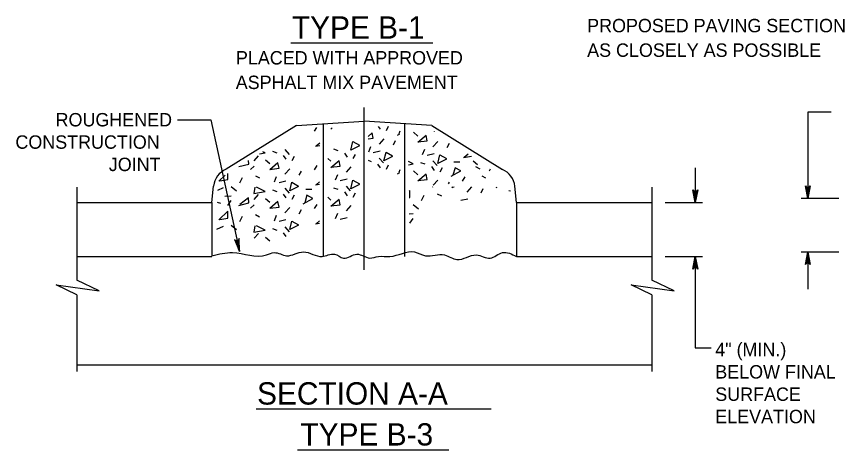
# Model space of a CAD drawing. Extents: x -7.6 to -0.4, y 98.1 to 108.3.
# Drawn here: x -7.303 to -3.651, y 104.4 to 106.341 of the extents above; entities that cross this region are included whole.
import ezdxf

# ---------------------------------------------------------------- set-up
doc = ezdxf.new("R2010")
doc.units = 0
for name, color, linetype in [('DETL-DIMS', 7, 'Continuous'), ('DETL-LINE', 7, 'Continuous'), ('DETL-NOTE', 7, 'Continuous'), ('DETL-PATT', 7, 'Continuous'), ('DETL-TITL', 7, 'Continuous')]:
    doc.layers.add(name, color=color, linetype=linetype)

msp = doc.modelspace()

# ---------------------------------------------------------------- linework, layer by layer
at = {"layer": 'DETL-DIMS'}
for p, q in [((-5.7445, 105.2058), (-5.7445, 105.9322)), ((-3.6535, 105.9115), (-3.7581, 105.9115)), ((-3.7581, 105.9115), (-3.7581, 105.5249)), ((-6.5803, 105.8778), (-6.432, 105.8778)), ((-6.432, 105.8778), (-6.3025, 105.2883)), ((-4.2616, 105.6624), (-4.2616, 105.5079)), ((-4.3961, 105.5079), (-4.2295, 105.5079)), ((-3.4196, 105.5249), (-3.7881, 105.5249)), ((-4.3961, 105.2655), (-4.2295, 105.2655)), ((-4.2616, 105.2655), (-4.2616, 104.8568)), ((-3.3833, 105.2855), (-3.7881, 105.2855)), ((-3.7581, 105.2855), (-3.7581, 105.1192)), ((-4.2616, 104.8568), (-4.1905, 104.8568))]:
    msp.add_line(p, q, dxfattribs=at)
for points in [[(-3.7581, 105.5249), (-3.7686, 105.5814), (-3.7656, 105.577), (-3.7618, 105.5748), (-3.7581, 105.5741), (-3.7543, 105.5748), (-3.7505, 105.577), (-3.7475, 105.5814), (-3.7581, 105.5249), (-3.7505, 105.577), (-3.7543, 105.5748), (-3.7581, 105.5249), (-3.7581, 105.5741), (-3.7618, 105.5748), (-3.7581, 105.5249), (-3.7656, 105.577)], [(-4.2616, 105.5079), (-4.2722, 105.5644), (-4.2692, 105.5601), (-4.2654, 105.5578), (-4.2616, 105.5572), (-4.2578, 105.5578), (-4.254, 105.5601), (-4.251, 105.5644), (-4.2616, 105.5079), (-4.254, 105.5601), (-4.2578, 105.5578), (-4.2616, 105.5079), (-4.2616, 105.5572), (-4.2654, 105.5578), (-4.2616, 105.5079), (-4.2692, 105.5601)], [(-6.3025, 105.2883), (-6.3043, 105.3457), (-6.3063, 105.3408), (-6.3095, 105.3378), (-6.3131, 105.3364), (-6.3169, 105.3362), (-6.3211, 105.3376), (-6.3249, 105.3412), (-6.3025, 105.2883), (-6.3211, 105.3376), (-6.3169, 105.3362), (-6.3025, 105.2883), (-6.3131, 105.3364), (-6.3095, 105.3378), (-6.3025, 105.2883), (-6.3063, 105.3408)], [(-4.2616, 105.2655), (-4.251, 105.209), (-4.254, 105.2134), (-4.2578, 105.2156), (-4.2616, 105.2163), (-4.2654, 105.2156), (-4.2692, 105.2134), (-4.2722, 105.209), (-4.2616, 105.2655), (-4.2692, 105.2134), (-4.2654, 105.2156), (-4.2616, 105.2655), (-4.2616, 105.2163), (-4.2578, 105.2156), (-4.2616, 105.2655), (-4.254, 105.2134)], [(-3.7581, 105.2855), (-3.7475, 105.229), (-3.7505, 105.2333), (-3.7543, 105.2356), (-3.7581, 105.2362), (-3.7618, 105.2356), (-3.7656, 105.2333), (-3.7686, 105.229), (-3.7581, 105.2855), (-3.7656, 105.2333), (-3.7618, 105.2356), (-3.7581, 105.2855), (-3.7581, 105.2362), (-3.7543, 105.2356), (-3.7581, 105.2855), (-3.7505, 105.2333)]]:
    msp.add_lwpolyline(points, dxfattribs=at)
at = {"layer": 'DETL-LINE'}
for p, q in [((-6.0475, 105.8514), (-5.7445, 105.8716)), ((-5.4415, 105.8514), (-5.7445, 105.8716)), ((-6.0475, 105.8514), (-6.363, 105.6558)), ((-5.9263, 105.2655), (-5.9263, 105.8594)), ((-5.5627, 105.2655), (-5.5627, 105.8594)), ((-5.4415, 105.8514), (-5.1259, 105.655)), ((-6.4263, 105.5079), (-6.419, 105.5807)), ((-5.0628, 105.5079), (-5.07, 105.58)), ((-7.0323, 105.5762), (-7.0323, 105.1599)), ((-4.4567, 105.5762), (-4.4567, 105.1599)), ((-7.0323, 105.5079), (-6.4263, 105.5079)), ((-6.4263, 105.5079), (-6.4263, 105.2685)), ((-5.0628, 105.5079), (-4.4567, 105.5079)), ((-5.0628, 105.5079), (-5.0628, 105.2655)), ((-7.0323, 105.2655), (-6.4263, 105.2655)), ((-5.0628, 105.2655), (-4.4567, 105.2655)), ((-7.0323, 105.0935), (-7.0323, 104.7507)), ((-4.4567, 105.0934), (-4.4567, 104.7507)), ((-7.0323, 104.7807), (-4.4567, 104.7807))]:
    msp.add_line(p, q, dxfattribs=at)
for points in [[(-7.032, 105.0934), (-7.1239, 105.1384), (-6.9317, 105.1122), (-7.032, 105.1599)], [(-4.4567, 105.0934), (-4.5486, 105.1384), (-4.3564, 105.1122), (-4.4567, 105.1599)]]:
    msp.add_lwpolyline(points, dxfattribs=at)
for centre, start, end in [((-6.3285, 105.5717), 112.2917, 174.2894), ((-5.1605, 105.5709), 5.7107, 67.6341)]:
    msp.add_arc(centre, 0.0909, start, end, dxfattribs=at)
msp.add_spline([(-6.4263, 105.2685), (-6.3341, 105.2827), (-6.1821, 105.2723), (-6.1476, 105.2827), (-6.0923, 105.2689), (-6.0164, 105.2861), (-5.9335, 105.2654), (-5.8782, 105.2758), (-5.8368, 105.2585), (-5.778, 105.2758), (-5.7193, 105.2585), (-5.6813, 105.2654), (-5.6295, 105.2654), (-5.519, 105.2861), (-5.4707, 105.2689), (-5.3843, 105.2723), (-5.3291, 105.2516), (-5.2427, 105.2723), (-5.1805, 105.2585), (-5.1253, 105.2827), (-5.0628, 105.2655)], degree=3, dxfattribs=at)
at = {"layer": 'DETL-PATT'}
for p, q in [((-5.9674, 105.8263), (-5.9569, 105.8431)), ((-5.8878, 105.8409), (-5.8935, 105.8359)), ((-5.6814, 105.8473), (-5.6732, 105.8358)), ((-5.6373, 105.8473), (-5.6467, 105.8286)), ((-5.5962, 105.8093), (-5.5855, 105.8152)), ((-5.5855, 105.8261), (-5.5889, 105.8141)), ((-5.5232, 105.8218), (-5.5039, 105.8049)), ((-5.4319, 105.8245), (-5.4317, 105.8242)), ((-5.9625, 105.7589), (-5.9433, 105.7621)), ((-5.9433, 105.7734), (-5.9602, 105.7589)), ((-5.6563, 105.7924), (-5.678, 105.7684)), ((-5.6058, 105.7828), (-5.6154, 105.7636)), ((-5.4149, 105.7809), (-5.4365, 105.7568)), ((-5.3643, 105.7713), (-5.3739, 105.752)), ((-6.1551, 105.7372), (-6.1359, 105.73)), ((-6.0998, 105.7445), (-6.0805, 105.7228)), ((-5.8814, 105.7469), (-5.8622, 105.7397)), ((-5.8333, 105.7277), (-5.8213, 105.7108)), ((-5.7165, 105.7563), (-5.7261, 105.7323)), ((-5.6732, 105.7371), (-5.7045, 105.7299)), ((-5.475, 105.7448), (-5.4847, 105.7207)), ((-5.4317, 105.7255), (-5.463, 105.7183)), ((-6.2369, 105.6939), (-6.2177, 105.7156)), ((-6.1864, 105.6987), (-6.1671, 105.6819)), ((-6.107, 105.718), (-6.0949, 105.7011)), ((-6.0588, 105.7132), (-6.0685, 105.6939)), ((-5.9074, 105.7038), (-5.8935, 105.6916)), ((-5.7852, 105.7228), (-5.7948, 105.7036)), ((-5.7272, 105.6963), (-5.7141, 105.6914)), ((-5.678, 105.7058), (-5.6587, 105.6841)), ((-5.4365, 105.6942), (-5.4173, 105.6726)), ((-5.3427, 105.6894), (-5.3162, 105.6894)), ((-5.2993, 105.7087), (-5.2646, 105.7145)), ((-5.2791, 105.724), (-5.2969, 105.7087)), ((-5.256, 105.6942), (-5.2368, 105.6774)), ((-6.2538, 105.6554), (-6.2369, 105.6698)), ((-6.0781, 105.6578), (-6.0998, 105.6337)), ((-5.9674, 105.653), (-5.9553, 105.6723)), ((-5.8044, 105.6675), (-5.8261, 105.6434)), ((-5.6852, 105.6793), (-5.6732, 105.6625)), ((-5.6371, 105.6745), (-5.6467, 105.6553)), ((-5.5855, 105.6528), (-5.5889, 105.6408)), ((-5.4919, 105.687), (-5.4726, 105.6798)), ((-5.4438, 105.6678), (-5.4317, 105.6509)), ((-5.3956, 105.6629), (-5.4052, 105.6437)), ((-5.2464, 105.6678), (-5.2271, 105.6581)), ((-5.1838, 105.6485), (-5.1785, 105.6578)), ((-6.367, 105.6295), (-6.3958, 105.6024)), ((-6.3019, 105.5952), (-6.2899, 105.6193)), ((-6.2321, 105.6265), (-6.2129, 105.6169)), ((-6.1383, 105.6217), (-6.1479, 105.5976)), ((-6.0275, 105.6482), (-6.0372, 105.6289)), ((-5.8646, 105.6314), (-5.8742, 105.6073)), ((-5.5962, 105.636), (-5.5855, 105.6419)), ((-5.5232, 105.6485), (-5.5039, 105.6317)), ((-5.3042, 105.6028), (-5.2921, 105.622)), ((-5.2175, 105.6268), (-5.2007, 105.6172)), ((-6.3404, 105.5784), (-6.3164, 105.5591)), ((-6.0949, 105.6024), (-6.1262, 105.5952)), ((-5.9625, 105.5856), (-5.9443, 105.5886)), ((-5.9443, 105.5992), (-5.9602, 105.5856)), ((-5.8213, 105.6121), (-5.8526, 105.6049)), ((-5.8261, 105.5808), (-5.8068, 105.5592)), ((-5.4149, 105.6076), (-5.4358, 105.5843)), ((-5.3643, 105.5979), (-5.3683, 105.5901)), ((-6.3765, 105.5736), (-6.4014, 105.5611)), ((-6.2369, 105.5206), (-6.2177, 105.5423)), ((-6.1551, 105.5639), (-6.1359, 105.5567)), ((-6.107, 105.5447), (-6.0949, 105.5278)), ((-6.0998, 105.5712), (-6.0805, 105.5495)), ((-6.0059, 105.5663), (-5.9794, 105.5663)), ((-5.8814, 105.5736), (-5.8622, 105.5664)), ((-5.8333, 105.5543), (-5.8213, 105.5375)), ((-5.7852, 105.5495), (-5.7948, 105.5303)), ((-5.4393, 105.5755), (-5.4378, 105.5767)), ((-5.4176, 105.5466), (-5.3983, 105.537)), ((-5.3526, 105.5755), (-5.3423, 105.5767)), ((-5.3484, 105.5767), (-5.3526, 105.5731)), ((-5.2646, 105.5767), (-5.2852, 105.5539)), ((-5.213, 105.5683), (-5.2226, 105.5491)), ((-5.1528, 105.5731), (-5.1506, 105.5767)), ((-5.0975, 105.5611), (-5.0897, 105.5589)), ((-6.403, 105.5081), (-6.3886, 105.5038)), ((-6.3693, 105.5351), (-6.3404, 105.5375)), ((-6.3549, 105.4941), (-6.3404, 105.5158)), ((-6.1864, 105.5254), (-6.1671, 105.5086)), ((-6.0588, 105.5399), (-6.0685, 105.5206)), ((-5.9074, 105.5305), (-5.8935, 105.5182)), ((-5.4874, 105.5154), (-5.4754, 105.5394)), ((-5.2804, 105.5226), (-5.3117, 105.5154)), ((-6.2538, 105.4821), (-6.2369, 105.4966)), ((-6.0781, 105.4845), (-6.0998, 105.4604)), ((-6.0275, 105.4749), (-6.0372, 105.4556)), ((-5.9674, 105.4797), (-5.9553, 105.4989)), ((-5.8044, 105.4942), (-5.8261, 105.4701)), ((-5.5259, 105.4985), (-5.5018, 105.4793)), ((-6.3019, 105.4219), (-6.2899, 105.446)), ((-6.2321, 105.4532), (-6.2129, 105.4436)), ((-6.1383, 105.4484), (-6.1479, 105.4243)), ((-5.8646, 105.4581), (-5.8742, 105.434)), ((-5.8213, 105.4388), (-5.8526, 105.4316)), ((-5.5437, 105.4561), (-5.5259, 105.4576)), ((-5.5403, 105.4143), (-5.5259, 105.4359)), ((-6.3765, 105.4003), (-6.4054, 105.3858)), ((-6.3404, 105.4051), (-6.3164, 105.3858)), ((-6.0949, 105.4292), (-6.1262, 105.4219)), ((-6.0998, 105.3979), (-6.0805, 105.3762)), ((-5.9625, 105.4123), (-5.9453, 105.4152)), ((-5.9453, 105.4251), (-5.9602, 105.4123)), ((-6.2369, 105.3473), (-6.2177, 105.369)), ((-6.1551, 105.3907), (-6.1359, 105.3834)), ((-6.107, 105.3714), (-6.0949, 105.3546)), ((-6.1864, 105.3521), (-6.1671, 105.3353))]:
    msp.add_line(p, q, dxfattribs=at)
for points in [[(-5.7272, 105.7922), (-5.7045, 105.7949), (-5.7093, 105.8189), (-5.7272, 105.8034)], [(-5.5039, 105.7785), (-5.463, 105.7833), (-5.4678, 105.8073), (-5.5039, 105.7761)], [(-5.7659, 105.7613), (-5.8044, 105.7421), (-5.7948, 105.7806), (-5.7659, 105.7638)], [(-6.2132, 105.7254), (-6.1888, 105.73), (-6.1982, 105.7347)], [(-5.6178, 105.713), (-5.6563, 105.6938), (-5.6467, 105.7323), (-5.6178, 105.7154)], [(-6.3058, 105.6677), (-6.261, 105.6795), (-6.2627, 105.6946)], [(-5.8935, 105.6651), (-5.8526, 105.6699), (-5.8574, 105.6939), (-5.8935, 105.6627)], [(-5.5469, 105.6757), (-5.5256, 105.6798), (-5.5469, 105.6904)], [(-5.3764, 105.7014), (-5.4149, 105.6822), (-5.4052, 105.7207), (-5.3764, 105.7039)], [(-6.1671, 105.6554), (-6.1262, 105.6602), (-6.131, 105.6843), (-6.1671, 105.653)], [(-5.3547, 105.6244), (-5.3114, 105.6485), (-5.3378, 105.6629), (-5.3475, 105.6292)], [(-6.391, 105.6049), (-6.3549, 105.6097), (-6.3549, 105.6371)], [(-5.5039, 105.6052), (-5.463, 105.61), (-5.4678, 105.6341), (-5.5039, 105.6028)], [(-6.0396, 105.5784), (-6.0781, 105.5591), (-6.0685, 105.5976), (-6.0396, 105.5808)], [(-5.7659, 105.5881), (-5.8044, 105.5688), (-5.7948, 105.6073), (-5.7659, 105.5904)], [(-6.2345, 105.576), (-6.2393, 105.5471), (-6.1888, 105.5567), (-6.2273, 105.576)], [(-5.5437, 105.5294), (-5.5403, 105.5298), (-5.5403, 105.5611), (-5.5437, 105.558)], [(-6.3067, 105.4941), (-6.261, 105.5062), (-6.2634, 105.5278), (-6.3019, 105.4989)], [(-6.1671, 105.4821), (-6.1262, 105.4869), (-6.131, 105.511), (-6.1671, 105.4797)], [(-6.0179, 105.5014), (-5.9746, 105.5254), (-6.0011, 105.5399), (-6.0107, 105.5062)], [(-5.8935, 105.4918), (-5.8526, 105.4966), (-5.8574, 105.5207), (-5.8935, 105.4894)], [(-6.391, 105.4316), (-6.3549, 105.4364), (-6.3549, 105.4677), (-6.3958, 105.4292)], [(-6.2345, 105.4027), (-6.2393, 105.3738), (-6.1888, 105.3834), (-6.2273, 105.4027)], [(-6.0396, 105.4051), (-6.0781, 105.3858), (-6.0685, 105.4243), (-6.0396, 105.4075)]]:
    msp.add_lwpolyline(points, dxfattribs=at)
at = {"layer": 'DETL-TITL'}
for p, q in [((-6.0731, 106.2222), (-5.4375, 106.2222)), ((-6.2287, 104.5838), (-5.1763, 104.5838)), ((-6.0438, 104.4005), (-5.366, 104.4005))]:
    msp.add_line(p, q, dxfattribs=at)

# ---------------------------------------------------------------- texts
at = {"layer": 'DETL-NOTE'}
for s, p in [('PROPOSED PAVING SECTION', (-4.746, 106.2693)), ('AS CLOSELY AS POSSIBLE', (-4.746, 106.1593)), ('PLACED WITH APPROVED', (-6.3191, 106.1251)), ('ASPHALT MIX PAVEMENT', (-6.3199, 106.0151)), ('ROUGHENED', (-7.1268, 105.8478)), ('CONSTRUCTION', (-7.3068, 105.7478)), ('JOINT', (-6.8884, 105.6478)), ('4" (MIN.)', (-4.1722, 104.819)), ('BELOW FINAL', (-4.1722, 104.719)), ('SURFACE', (-4.1722, 104.619)), ('ELEVATION', (-4.1722, 104.519))]:
    msp.add_text(s, height=0.06, dxfattribs=at).set_placement(p)
at = {"layer": 'DETL-TITL'}
for s, p in [('TYPE B-1', (-6.0685, 106.2408)), ('SECTION A-A', (-6.2245, 104.6024)), ('TYPE B-3', (-6.0303, 104.4191))]:
    msp.add_text(s, height=0.1, dxfattribs=at).set_placement(p)

doc.saveas('drawing.dxf')
